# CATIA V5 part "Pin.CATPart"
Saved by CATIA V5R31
Part number: Pin
Bounding box of the stored display mesh (mm): x -15 to 15, y -15 to 15, z -50 to 0
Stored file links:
  D:\PROJECTS\Project 2021\US EDITION\CATIA V5 6R 2021\Resources\Part Files\c12_catia_v5_6r2021_prt\c12_catia_v5-6r2021 figr_12-30\Pin.CATPart
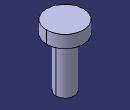
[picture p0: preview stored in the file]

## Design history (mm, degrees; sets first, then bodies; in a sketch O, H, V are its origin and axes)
Body1 (main body)
  Sketch1 on xy-plane, origin (0, 0, 0), H (1, 0, 0), V (0, 1, 0)
    circle A1 centre (0, 0) radius 15
    circle A2 centre (0, 0) radius 7.5
    radius A2 = 7.5
    radius A1 = 15
  MultiPad1: profile Sketch1, domains (length -50; length -10)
